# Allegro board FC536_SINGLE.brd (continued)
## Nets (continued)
HSIO171PB0: TP249.1(TP) U1.AG3(HSIO171PB0-DDR_N_0_DQS_P-NW_PLL)
HSIO172NB0: TP250.1(TP) U1.AG1(HSIO172NB0-DDR_N_0_DQ)
HSIO172PB0: TP251.1(TP) U1.AF1(HSIO172PB0-DDR_N_0_DQ-PIO_CLKIN)
HSIO173NB0: TP252.1(TP) U1.AD4(HSIO173NB0-DDR_N_0_DQ-NW_DTEST_)
HSIO173PB0: TP253.1(TP) U1.AF3(HSIO173PB0-DDR_N_0_DQ-PIO_CLKIN)
JTAG_TCK: TP314.1(TP) U1.L11(JTAG_TCK)
JTAG_TDI: TP315.1(TP) U1.K11(JTAG_TDI)
JTAG_TDO: TP316.1(TP) U1.L8(JTAG_TDO)
JTAG_TMS: TP317.1(TP) U1.L9(JTAG_TMS)
JTAG_TRSTB: TP318.1(TP) U1.H10(JTAG_TRSTB)
SC_EXIT_FLASH_FREEZE_B: TP326.1(TP) U1.H11(SC_EXIT_FLASH_FREEZE_B)
SC_IO_CFG_INTERFACE: TP325.1(TP) U1.J11(SC_IO_CFG_INTERFACE)
SC_SPI_ENABLE: TP324.1(TP) U1.L17(SC_SPI_ENABLE)
SC_SPI_SCK: TP323.1(TP) U1.L14(SC_SPI_SCK)
SC_SPI_SDI: TP322.1(TP) U1.K13(SC_SPI_SDI)
SC_SPI_SDO: TP321.1(TP) U1.K14(SC_SPI_SDO)
SC_SPI_SS: TP320.1(TP) U1.K8(SC_SPI_SS)
SERDES_0_INT_REFCLK_N: TP348.1(TP) U1.U28(SERDES_0_INT_REFCLK_N)
SERDES_0_INT_REFCLK_P: TP347.1(TP) U1.U27(SERDES_0_INT_REFCLK_P)
SERDES_0_RX0_N: TP328.1(TP) U1.G30(SERDES_0_RX0_N)
SERDES_0_RX0_P: TP327.1(TP) U1.H30(SERDES_0_RX0_P)
SERDES_0_RX1_N: TP330.1(TP) U1.K30(SERDES_0_RX1_N)
SERDES_0_RX1_P: TP329.1(TP) U1.L30(SERDES_0_RX1_P)
SERDES_0_RX2_N: TP332.1(TP) U1.Y30(SERDES_0_RX2_N)
SERDES_0_RX2_P: TP331.1(TP) U1.AA30(SERDES_0_RX2_P)
SERDES_0_RX3_N: TP334.1(TP) U1.AC30(SERDES_0_RX3_N)
SERDES_0_RX3_P: TP333.1(TP) U1.AD30(SERDES_0_RX3_P)
SERDES_0_TX0_N: TP340.1(TP) U1.D30(SERDES_0_TX0_N)
SERDES_0_TX0_P: TP339.1(TP) U1.E30(SERDES_0_TX0_P)
SERDES_0_TX1_N: TP342.1(TP) U1.N30(SERDES_0_TX1_N)
SERDES_0_TX1_P: TP341.1(TP) U1.P30(SERDES_0_TX1_P)
SERDES_0_TX2_N: TP344.1(TP) U1.U30(SERDES_0_TX2_N)
SERDES_0_TX2_P: TP343.1(TP) U1.V30(SERDES_0_TX2_P)
SERDES_0_TX3_N: TP346.1(TP) U1.AG30(SERDES_0_TX3_N)
SERDES_0_TX3_P: TP345.1(TP) U1.AF30(SERDES_0_TX3_P)
SERDES_0N_EXT_REFCLK_N: TP336.1(TP) U1.Y27(SERDES_0N_EXT_REFCLK_N)
SERDES_0N_EXT_REFCLK_P: TP335.1(TP) U1.Y28(SERDES_0N_EXT_REFCLK_P)
SERDES_0S_EXT_REFCLK_N: TP338.1(TP) U1.P28(SERDES_0S_EXT_REFCLK_N)
SERDES_0S_EXT_REFCLK_P: TP337.1(TP) U1.P27(SERDES_0S_EXT_REFCLK_P)
SERDES_VREF: C98.1 C99.1 U1.L27(SERDES_VREF_1) U1.L28(SERDES_VREF_2)

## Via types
v1: diameter 0.305, hole 0.152, TOP to BOTTOM, 372 vias

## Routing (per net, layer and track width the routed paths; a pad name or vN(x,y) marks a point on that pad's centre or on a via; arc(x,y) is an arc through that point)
GND: length 84.5
  TOP w0.203: U1.AG13 v1(56.78,50.75) ; U1.E1 v1(50.22,61.96) ; U1.V4 v1(51.85,55.25) ; U1.N19 v1(59.28,57.68) U1.P18 ; U1.T30 v1(65.41,56.46) ; U1.L24 v1(62.28,59.18) U1.K25 ; U1.N12 v1(56.28,57.75) ; U1.A1 v1(50.57,64.31) ; U1.Y21 v1(60.35,54.25) ; U1.V21 v1(60.28,55.75) U1.U20 ; U1.L26 v1(63.28,59.18) ; U1.U24 v1(62.28,55.75) ; U1.Y23 v1(61.78,54.25) ; U1.N23 v1(61.28,57.68) U1.P22 ; U1.AE30 v1(65.41,51.96) ; U1.P20 v1(60.28,57.68) U1.N21 ; U1.AG24 v1(62.28,50.75) ; U1.E21 v1(60.78,62.18) ; U1.P6 v1(52.85,57.25) ; U1.AD7 v1(53.35,52.25) ; U1.K28 v1(64.28,59.68) ; v1(63.35,54.18) U1.AA27 U1.AA28 ; U1.R1 v1(50.22,56.96) ; U1.J14 v1(56.85,60.18) ; U1.AA5 v1(52.35,53.75) ; U1.AA23 v1(61.78,53.75) ; U1.K5 52.42,59.61 52.42,59.66 v1(52.36,59.72) ; U1.AK26 v1(63.07,49.12) ; U1.V26 v1(62.78,55.75) U1.U25 ; U1.N17 v1(58.78,58.18) ; v1(64.75,58.31) 64.9,58.46 U1.M30 ; U1.A26 v1(63.07,64.31) ; U1.AE1 v1(50.22,51.96) ; U1.K22 v1(60.85,59.25) ; U1.R30 64.93,56.96 v1(64.74,57.15) ; U1.N27 63.5,57.96 v1(63.28,57.75) U1.N26 ; U1.G7 v1(53.35,61.18) ; 64.05,55.46 v1(64.26,55.24) ; U1.AF21 v1(60.78,51.25) ; U1.A16 v1(58.07,64.31) ; U1.V14 v1(57.28,55.25) ; U1.AC26 v1(63.28,52.75) ; U1.P25 v1(62.78,57.68) ; U1.U13 v1(56.78,56.18) ; U1.H24 v1(62.28,60.68) ; U1.L23 v1(61.78,59.18) ; U1.AA25 v1(62.78,53.75) ; U1.J30 v1(65.41,59.96) ; U1.V27 U1.V28 ; U1.K10 v1(55.28,59.25) ; U1.N28 v1(64.28,58.18) ; U1.N14 v1(57.28,58.18) ; U1.V17 v1(58.78,55.68) ; U1.Y26 v1(63.28,54.68) ; U1.D4 v1(51.85,62.68) ; U1.P11 v1(55.35,57.68) ; U1.AK6 v1(53.07,49.12) ; U1.P24 v1(62.28,57.68) ; U1.AE17 v1(58.78,51.75) ; U1.A6 v1(53.07,64.31) ; U1.V12 v1(56.28,55.68) ; U1.H26 v1(63.28,60.68) ; U1.M18 v1(59.28,58.68) ; U1.F17 v1(58.78,61.68) ; U1.F30 v1(65.41,61.46) ; U1.H28 v1(64.28,60.68) ; U1.AF26 v1(63.28,51.25) ; U1.C30 v1(65.41,62.96) ; U1.U11 v1(55.35,56.18) ; U1.P13 v1(56.78,57.68) ; U1.V19 v1(59.28,55.75) U1.U18 ; U1.AF10 v1(54.85,51.25) ; U1.AC28 v1(64.28,52.75) ; U1.AK16 v1(58.07,49.12) ; U1.AA10 v1(54.85,53.75) ; U1.AB30 v1(65.41,53.46) ; U1.W30 v1(65.41,54.96) ; U1.W18 v1(58.85,54.75) ; U1.AK30 v1(65.07,49.12) ; U1.D13 v1(56.35,62.68) ; U1.U22 v1(61.28,55.75) U1.V23 ; U1.K23 v1(61.35,59.68) ; U1.W13 v1(56.35,54.75) ; U1.AB14 v1(56.85,53.25) ; U1.E10 v1(54.85,62.18) ; U1.K27 v1(63.78,59.68) ; U1.Y24 v1(62.28,54.25) ; U1.AC24 v1(62.28,52.75) ; U1.E26 v1(63.28,62.18) ; U1.AH30 v1(65.41,50.46) ; U1.AG4 v1(51.85,50.75) ; U1.D24 v1(61.85,62.68)
  BOTTOM w0.203: v1(53.35,52.25) 53.74,52.63 53.74,52.92 53.62,53.04 C54.1
  BOTTOM w0.254: C46.1 58.37,61.53 58.53,61.68 v1(58.78,61.68) 58.83,61.72 C73.2 ; C50.1 59.59,58.68 v1(59.28,58.68) 59.24,58.63 C17.1 ; v1(54.85,62.18) 55.01,62.02 C75.2 ; C59.2 56.82,53.28 v1(56.85,53.25) 57.64,53.25 C10.1 ; v1(61.78,54.25) 61.51,54.52 C19.1 ; C13.1 56.61,57.51 v1(56.78,57.68) ; v1(63.28,51.25) 63.2,51.33 C24.1 ; C56.2 50.5,47.6 v1(50.51,47.58) ; C66.2 62.31,50.72 v1(62.28,50.75) 62.33,50.8 C65.2 ; C51.1 58.78,58.17 v1(58.78,58.18) ; v1(63.28,59.18) 63.34,59.12 C32.1 ; C90.2 52.15,53.95 v1(52.35,53.75) 52.38,53.72 C63.2 ; v1(58.78,55.68) 59.19,56.08 C9.1 ; v1(51.85,62.68) 52.07,62.9 C94.2 ; C43.1 62.5,56.03 v1(62.78,55.75) ; C96.2 64.25,58.22 v1(64.28,58.18) ; v1(55.35,57.68) 55.18,57.5 C52.1 ; C2.1 56.78,56.52 v1(56.78,56.18) ; C15.1 60.81,59.2 v1(60.85,59.25) ; v1(51.85,50.75) 51.85,50.75 C21.1 ; C35.1 64.18,60.58 v1(64.28,60.68) ; v1(64.28,52.75) 64.36,52.82 C41.1 ; C30.1 61,51.25 v1(60.78,51.25) 60.77,51.26 C67.2 ; C12.1 54.45,55.22 v1(54.34,55.11) 53.96,55.11 C22.1 ; C1.1 56.43,55.9 56.28,55.75 v1(56.28,55.68) ; C68.2 58.83,51.79 v1(58.78,51.75) 58.83,51.7 C69.2 ; C27.1 55.09,59.44 v1(55.28,59.25) 55.32,59.21 C85.2 ; C8.1 59.11,56.72 v1(58.85,56.97) ; C62.2 56.92,50.88 v1(56.78,50.75) ; v1(61.72,56.72) 61.7,56.74 C14.1 ; C58.2 52.83,50.41 v1(52.99,50.25) ; C3.1 61.31,57.65 v1(61.28,57.68) 61.42,57.82 C38.1 ; C77.2 53.31,64.07 v1(53.07,64.31) ; v1(62.78,57.68) 62.56,57.45 C44.1 ; v1(64.75,58.31) 64.75,58.35 64.87,58.46 C99.2 ; v1(60.78,62.18) 60.76,62.2 C82.2 ; v1(48.6,54.47) 48.62,54.48 C87.2 ; v1(57.94,55.93) 58.17,55.7 C16.1 ; v1(57.86,57.99) 57.76,57.89 C29.1 ; v1(54.85,53.75) 54.86,53.75 C64.2 ; C95.2 52.3,59.57 52.36,59.62 v1(52.36,59.72) 52.36,59.75 52.7,60.1 52.72,60.1 52.77,60.15 C53.1 ; C89.2 C91.2 52.75,57.35 v1(52.85,57.25) ; v1(56.35,62.68) 56.41,62.73 C74.2 ; C76.2 66.95,63.96 v1(66.97,63.97) ; C84.2 53.48,58.67 v1(53.43,58.62) ; v1(57.28,58.18) 57.4,58.3 C48.1 ; C25.1 60.27,54.33 v1(60.35,54.25) ; v1(64.73,53.6) 64.73,53.59 C36.1 ; v1(63.28,52.75) 63.11,52.92 C42.1 ; C39.1 61.35,55.69 v1(61.28,55.75) 61.26,55.77 C6.1 ; v1(61.78,53.75) 61.87,53.66 C71.2 ; v1(61.78,59.18) 61.85,59.18 62.02,59.01 C72.2 ; C80.2 63.08,62.38 v1(63.28,62.18) ; C7.1 59.39,55.64 v1(59.28,55.75) ; v1(59.28,57.68) 59.21,57.61 C5.1 ; C45.1 62.48,60.37 62.28,60.56 v1(62.28,60.68) ; v1(55.56,65.9) 55.58,65.89 C79.2 ; C57.2 55.58,47.6 v1(55.59,47.58) ; v1(58.85,54.75) 58.83,54.72 C20.1 ; C61.2 54.97,51.36 v1(54.85,51.25) 54.64,51.25 54.38,51.5 C31.1 ; C11.1 56.35,54.74 v1(56.35,54.75) 56.67,54.75 C18.1 ; C47.1 53.42,61.25 v1(53.35,61.18) ; v1(64.26,55.24) 64.24,55.22 C97.2 ; C86.2 50.54,52.28 v1(50.22,51.96) ; v1(57.28,55.25) 57.33,55.29 C23.1 ; C55.1 56.23,57.8 v1(56.28,57.75) ; C60.2 53.29,49.34 v1(53.07,49.12) ; C4.1 57.87,56.84 v1(57.84,56.87) 57.82,56.89 C28.1 ; C37.1 62.82,56.76 v1(62.76,56.82) ; v1(60.56,65.93) 60.58,65.91 C78.2 ; v1(61.35,59.68) 61.24,59.79 C26.1 ; C98.2 65.34,60.04 v1(65.41,59.96) ; v1(64.74,57.15) 64.95,56.94 C40.1 ; v1(48.65,59.45) 48.67,59.46 C92.2 ; v1(49.72,60.27) 49.73,60.26 C93.2 ; C83.2 62.2,62.33 v1(61.85,62.68) ; C88.2 51.85,55.25 v1(51.85,55.25) ; C49.1 56.82,60.15 v1(56.85,60.18) 56.92,60.11 C81.2 ; C70.2 60.58,47.57 v1(60.59,47.56) ; v1(62.28,54.25) 62.16,54.37 C33.1 ; C34.1 62.34,59.23 v1(62.28,59.18)
VDD: length 13.8
  TOP w0.203: U1.P12 v1(55.85,57.68) ; U1.V22 v1(60.85,55.25) ; U1.V18 v1(58.85,55.25) ; U1.V13 v1(56.35,55.25) ; U1.N13 v1(56.78,58.18) ; U1.U21 v1(60.78,55.75) ; U1.V11 v1(55.35,55.68) ; U1.N18 v1(58.85,57.75) ; U1.N20 v1(60.28,58.18) ; U1.P19 v1(59.78,57.68) ; U1.P14 v1(57.28,57.68) ; U1.U19 v1(59.78,55.75) ; U1.P21 v1(60.78,57.68) ; U1.V20 v1(60.28,55.25) ; U1.W17 v1(58.35,54.75) ; U1.U12 v1(55.85,55.75) ; U1.N22 v1(60.85,58.18) ; U1.U17 v1(58.35,56.18)
  BOTTOM w0.203: v1(58.35,54.75) 57.96,54.35 57.96,54.17 C10.2
  BOTTOM w0.254: C17.2 60.27,58.17 v1(60.28,58.18) ; C9.2 59.79,55.75 v1(59.78,55.75) ; C4.2 58.47,56.29 v1(58.35,56.18) ; C11.2 55.85,55.75 v1(55.85,55.75) 55.83,55.77 C1.2 ; v1(56.35,55.25) 56.4,55.25 56.65,55.49 C18.2 ; C14.2 60.47,56.74 v1(60.21,57) ; C3.2 60.71,57.61 v1(60.78,57.68) ; C6.2 60.66,55.87 v1(60.78,55.75) ; C15.2 60.81,58.22 v1(60.85,58.18) ; C7.2 60.24,55.3 v1(60.28,55.25) ; v1(55.58,56.7) 55.58,56.69 C2.2 ; C8.2 59.95,56.72 v1(60.21,56.45) ; C12.2 55.24,55.57 v1(55.35,55.68) ; v1(58.85,55.25) 58.83,55.23 58.45,55.23 C16.2 ; v1(55.85,57.68) 55.85,57.44 C13.2 ; v1(59.78,57.68) 59.81,57.65 C5.2
VDD18: length 5.1
  TOP w0.203: U1.Y9 v1(54.35,54.25) ; U1.W14 v1(57.28,54.75) ; U1.AF4 v1(51.85,51.25) ; U1.Y22 v1(60.85,54.25) ; U1.AF27 v1(63.78,51.25) ; U1.Y20 v1(59.85,54.25) ; U1.Y18 v1(59.28,54.25)
  BOTTOM w0.203: C20.2 58.89,53.85 v1(59.28,54.25)
  BOTTOM w0.254: v1(57.28,54.75) 57.34,54.69 C23.2 ; C24.2 63.8,51.26 v1(63.78,51.25) ; C19.2 60.91,54.31 v1(60.85,54.25) ; v1(59.85,54.25) 59.67,54.43 C25.2 ; v1(51.85,51.25) 51.75,51.35 C21.2 ; v1(54.35,54.25) 54.24,54.36 C22.2
VDD25: length 4.8
  TOP w0.203: U1.AC8 v1(54.28,52.75) ; U1.J10 v1(55.28,60.18) ; U1.H23 v1(61.78,60.68) ; U1.U14 v1(57.28,55.75) ; U1.P17 v1(58.35,57.25) ; U1.AC23 v1(61.35,52.75)
  BOTTOM w0.254: v1(57.28,55.75) 57.28,55.75 C28.2 ; C31.2 54.38,52.65 v1(54.28,52.75) ; C30.2 61.26,52.66 v1(61.35,52.75) ; C27.2 55.15,60.04 v1(55.28,60.18) ; C26.2 61.61,60.85 v1(61.78,60.68) ; C29.2 58.36,57.26 v1(58.35,57.25)
VDDA: length 7.1
  TOP w0.203: U1.AA26 v1(63.28,53.75) ; U1.H27 v1(63.78,60.68) ; U1.L25 v1(62.78,59.18) ; U1.P26 v1(63.28,57.25) ; U1.Y25 v1(62.78,54.25) ; U1.K26 v1(63.28,59.68) ; U1.U26 v1(63.28,55.75) ; U1.N24 v1(62.28,58.18) ; U1.V24 v1(62.28,55.25) ; U1.AC27 v1(63.78,52.75)
  BOTTOM w0.254: v1(63.28,53.75) 63.43,53.75 63.58,53.59 C36.2 ; v1(62.28,58.18) 62.27,58.19 C38.2 ; v1(63.78,52.75) 63.76,52.77 C41.2 ; v1(63.28,55.75) 63.17,55.86 C37.2 ; v1(63.78,60.68) 63.78,60.58 63.65,60.45 63.65,60.25 C35.2 ; v1(63.86,56.7) 63.88,56.72 C40.2 ; v1(62.78,59.18) 62.78,58.89 C32.2 ; C33.2 62.76,54.27 v1(62.78,54.25) ; C34.2 63.24,59.64 v1(63.28,59.68) ; C39.2 62.28,55.24 v1(62.28,55.25)
VDDA25: length 3.3
  TOP w0.203: U1.U23 v1(61.78,55.75) ; U1.AA24 v1(62.28,53.75) ; U1.P23 v1(61.78,57.68) ; U1.K24 v1(61.85,59.68)
  BOTTOM w0.254: v1(62.28,53.75) 62.38,53.65 62.38,53.4 C42.2 ; C43.2 61.9,55.87 v1(61.78,55.75) ; v1(61.78,57.68) 61.96,57.51 C44.2 ; C45.2 61.85,60.2 v1(61.85,59.68)
VDDAUX2: length 4.6
  TOP w0.203: U1.G18 v1(59.28,61.18) ; U1.M17 v1(58.78,58.68) ; U1.L13 v1(56.78,58.75) ; U1.M14 v1(57.28,58.68) ; U1.L18 v1(59.28,59.18) ; U1.H8 v1(54.28,60.68)
  BOTTOM w0.254: C48.2 57.53,58.9 57.31,58.68 v1(57.28,58.68) ; v1(56.78,58.75) 56.82,58.78 C49.2 ; C47.2 54.14,60.83 v1(54.28,60.68) ; C51.2 58.69,58.77 v1(58.78,58.68) ; C50.2 59.62,59.31 59.41,59.31 v1(59.28,59.18) ; C46.2 59.25,61.21 v1(59.28,61.18)
VDDAUX4: length 3.3
  TOP w0.203: U1.K9 v1(54.35,59.68) ; U1.U10 54.89,56.14 v1(54.89,56.41) ; U1.AA9 v1(54.35,53.75) ; U1.N11 v1(55.35,58.18)
  BOTTOM w0.254: v1(54.35,59.68) 54.35,59.87 C53.2 ; C54.2 54.22,53.62 v1(54.35,53.75) ; C52.2 54.75,56.55 v1(54.89,56.41) ; C55.2 55.39,58.14 v1(55.35,58.18)
VDDI0: length 7.4
  TOP w0.203: U1.AC7 v1(53.35,52.75) ; U1.AK1 v1(50.57,49.12) ; U1.AF5 v1(52.35,51.25) ; U1.AH8 v1(54.07,50.12) ; U1.AK11 v1(55.57,49.12) ; U1.AE14 v1(56.85,51.75) ; U1.AD11 v1(55.78,52.25) ; U1.Y13 v1(56.35,54.25) ; U1.Y10 v1(54.85,54.25)
  BOTTOM w0.254: v1(55.57,49.12) 55.58,49.11 C57.1 ; C58.1 52.46,51.35 v1(52.35,51.25) ; C62.1 57.12,51.48 v1(56.85,51.75) ; v1(55.78,52.25) 55.61,52.25 C61.1 ; C56.1 50.5,49.04 v1(50.57,49.12) ; v1(54.07,50.12) 53.89,49.94 C60.1 ; v1(56.35,54.25) 56.35,54.25 C59.1 ; C64.1 54.96,54.35 v1(54.85,54.25) ; C63.1 53.1,53.17 53.1,53.05 53.35,52.79 v1(53.35,52.75)
VDDI1: length 5.3
  TOP w0.203: U1.AA22 v1(60.85,53.75) ; U1.AG27 v1(63.78,50.75) ; U1.AG18 v1(59.28,50.75) ; U1.AB17 v1(58.78,53.25) ; U1.AK21 v1(60.57,49.12) ; U1.AD24 v1(62.28,52.25) ; U1.AD20 v1(60.28,52.25)
  BOTTOM w0.254: C68.1 58.83,53.2 v1(58.78,53.25) ; C67.1 60.33,52.21 v1(60.28,52.25) ; C66.1 63.76,50.72 v1(63.78,50.75) ; v1(59.28,50.75) 59.18,50.86 C69.1 ; v1(62.28,52.25) 62.33,52.2 C65.1 ; C71.1 61.23,53.37 v1(60.85,53.75) ; v1(60.57,49.12) 60.58,49.11 C70.1
VDDI2: length 9.8
  TOP w0.203: U1.G11 v1(55.78,61.18) ; U1.A30 v1(65.41,63.96) ; U1.A21 v1(60.57,64.31) ; U1.D27 v1(63.78,62.68) ; U1.G20 v1(60.28,61.18) ; U1.L22 v1(61.28,59.18) ; U1.D18 v1(59.28,62.68) ; U1.J17 v1(58.78,59.75) ; U1.F14 v1(56.85,61.68) ; U1.A11 v1(55.57,64.31) ; U1.G24 v1(62.28,61.18) ; U1.C8 v1(53.85,63.18)
  BOTTOM w0.254: C81.1 58.64,59.75 v1(58.78,59.75) ; v1(60.57,64.31) 60.58,64.3 C78.1 ; C76.1 65.42,63.96 v1(65.41,63.96) ; C73.1 59.26,62.66 v1(59.28,62.68) ; v1(55.57,64.31) 55.58,64.32 C79.1 ; v1(56.85,61.68) 56.82,61.71 C74.1 ; v1(53.85,63.18) 53.86,63.18 C77.1 ; v1(63.78,62.68) 63.78,62.75 C80.1 ; v1(60.28,61.18) 60.33,61.22 C82.1 ; v1(62.28,61.18) 62.33,61.23 C83.1 ; v1(55.78,61.18) 55.56,61.18 C75.1 ; C72.1 61.42,59.04 v1(61.28,59.18)
VDDI3: length 1.7
  TOP w0.203: U1.L10 v1(54.85,58.75) ; U1.M13 v1(56.35,58.68)
  BOTTOM w0.254: v1(54.85,58.75) 54.78,58.67 C84.1 ; v1(56.35,58.68) 56.21,58.83 C85.1
VDDI4: length 8.3
  TOP w0.203: U1.L7 v1(53.35,59.18) ; U1.H3 v1(51.35,60.25) ; U1.P10 v1(54.85,57.68) ; U1.N4 v1(51.85,58.18) ; U1.K1 v1(50.22,59.46) ; U1.Y7 v1(53.35,54.25) ; U1.U6 v1(52.85,55.75) ; U1.E5 v1(52.35,62.18) ; U1.AC3 v1(51.22,52.96) ; U1.Y1 v1(50.22,54.46)
  BOTTOM w0.254: C93.1 51.34,60.26 v1(51.35,60.25) ; C91.1 51.85,58.01 v1(51.85,58.18) ; C88.1 52.81,55.7 v1(52.85,55.75) ; C90.1 53.31,54.2 v1(53.35,54.25) ; v1(50.22,54.46) 50.2,54.48 C87.1 ; C94.1 52.64,62.46 v1(52.35,62.18) ; v1(54.85,57.68) 54.82,57.71 C89.1 ; C92.1 50.22,59.46 v1(50.22,59.46) ; v1(53.35,59.18) 53.32,59.21 C95.1 ; C86.1 51.14,52.88 v1(51.22,52.96)
VDDSREF: length 1.4
  TOP w0.203: U1.V25 v1(62.78,55.25) ; U1.N25 v1(62.78,58.18)
  BOTTOM w0.254: C97.1 62.81,55.22 v1(62.78,55.25) ; v1(62.78,58.18) 62.82,58.22 C96.1
DEVRST_N: length 7.2
  TOP w0.076: U1.J13 v1(56.35,60.18)
  SIG2 w0.076: v1(56.35,60.18) 56.64,59.89 56.99,59.89 57.23,60.13 57.23,61.8 56.85,62.18 56.85,65.79
GPIO0NB2: length 4.8
  TOP w0.076: U1.G14 v1(56.85,61.18)
  SIG1 w0.076: v1(56.85,61.18) 56.89,61.18 57.17,61.46 57.17,61.9 56.97,62.1 56.97,62.32 57.08,62.43 57.08,65.37
GPIO0PB2: length 5.2
  TOP w0.076: U1.H14 v1(56.85,60.68)
  SIG1 w0.076: v1(56.85,60.68) 57.58,61.41 57.58,65.3
GPIO1NB2: length 3.4
  TOP w0.076: U1.C14 56.83,63.2 56.83,66.22
GPIO1PB2: length 3.4
  TOP w0.076: 56.33,66.22 56.33,63.2 U1.C13
GPIO2NB2: length 3.7
  TOP w0.076: U1.E13 v1(56.35,62.18)
  SIG1 w0.076: v1(56.35,62.18) 56.35,62.28 56.67,62.6 56.67,65.44 56.7,65.46 56.7,65.48
GPIO2PB2: length 4.2
  TOP w0.076: U1.F13 v1(56.35,61.68)
  SIG1 w0.076: v1(56.35,61.68) 56.75,62.08 56.75,62.39 56.88,62.51 56.88,65.35
GPIO3NB2: length 2.3
  TOP w0.076: U1.A14 57.07,66.22
GPIO3PB2: length 2.3
  TOP w0.076: U1.A15 57.57,66.22
GPIO4NB2: length 4.7
  TOP w0.076: U1.G13 v1(56.35,61.18)
  SIG1 w0.076: 56.38,65.33 56.38,64.1 56.09,63.8 56.09,62.8 56.08,62.79 56.08,61.56 56.09,61.55 56.09,61.45 v1(56.35,61.18)
GPIO4PB2: length 5.5
  TOP w0.076: U1.H13 v1(56.35,60.68)
  SIG2 w0.076: 56.07,65.79 56.07,60.96 v1(56.35,60.68)
GPIO5NB2: length 3.9
  TOP w0.076: U1.D14 57.33,62.72 57.33,63.86 57.33,63.86 57.33,66.22
GPIO5PB2: length 3.4
  TOP w0.076: U1.E14 v1(57.28,62.18)
  SIG1 w0.076: v1(57.28,62.18) 57.28,65.3
GPIO6NB2: length 7.1
  TOP w0.076: U1.L21 v1(60.35,59.18)
  SIG1 w0.076: 66.83,59.23 64.9,59.23 64.52,58.85 60.68,58.85 v1(60.35,59.18)
GPIO6PB2: length 7.1
  TOP w0.076: U1.L20 v1(60.28,58.75)
  SIG1 w0.076: v1(60.28,58.75) 60.38,58.65 65.22,58.65 65.48,58.9 66.93,58.9
GPIO7NB2: length 6.4
  TOP w0.076: U1.J18 v1(58.85,60.18)
  SIG2 w0.076: v1(58.85,60.18) 58.41,60.18 58.06,60.52 58.06,60.81 58.24,60.99 58.24,61.8 58.78,62.33 58.78,65.41
GPIO7PB2: length 5.5
  TOP w0.076: U1.H18 v1(59.28,60.68)
  SIG1 w0.076: 59.03,65.3 59.03,63.65 58.45,63.08 58.45,61.51 v1(59.28,60.68)
GPIO8NB2: length 5.1
  TOP w0.076: U1.H17 v1(58.35,60.68)
  SIG1 w0.076: v1(58.35,60.68) 58.04,60.99 58.04,63.32 58.57,63.86 58.57,65.13
GPIO8PB2: length 5.1
  TOP w0.076: U1.G17 v1(58.78,60.75)
  SIG1 w0.076: v1(58.78,60.75) 58.24,61.29 58.24,63.24 58.78,63.77 58.78,65.13
GPIO9NB2: length 6.5
  TOP w0.076: v1(58.22,59.39) 58.3,59.46 U1.K17
  SIG1 w0.076: v1(58.22,59.39) 58.22,59.65 57.74,60.14 57.74,61.28 57.78,61.32 57.78,65.3
GPIO9PB2: length 8.5
  TOP w0.076: U1.K18 v1(59.28,59.68)
  SIG2 w0.076: v1(59.28,59.68) 59.8,59.16 59.8,58.79 60.13,58.47 60.55,58.47 60.88,58.8 66.62,58.8
GPIO10NB2: length 6.5
  TOP w0.076: U1.K21 v1(60.78,59.68)
  SIG1 w0.076: v1(60.78,59.68) 61.08,59.98 64.99,59.98 65.33,59.64 66.7,59.64
GPIO10PB2: length 6.7
  TOP w0.076: U1.K20 v1(60.28,59.68)
  SIG2 w0.076: 66.32,60.43 65.15,60.43 64.74,60.02 60.62,60.02 v1(60.28,59.68)
GPIO11NB2: length 5.6
  TOP w0.076: U1.H20 v1(60.28,60.68)
  SIG2 w0.076: v1(60.28,60.68) 59.98,60.98 59.98,61.38 60.24,61.63 60.24,65.75
GPIO11PB2: length 6
  TOP w0.076: U1.J20 v1(59.85,60.18)
  SIG2 w0.076: 59.56,65.75 59.56,60.47 v1(59.85,60.18)
GPIO12NB2: length 3.5
  TOP w0.076: U1.E18 v1(59.28,62.18)
  SIG1 w0.076: 59.58,65.25 59.58,62.48 v1(59.28,62.18)
GPIO12PB2: length 4.4
  TOP w0.076: U1.F18 v1(59.28,61.68)
  SIG1 w0.076: 59.23,65.43 59.23,63.4 58.83,62.99 58.83,62.14 v1(59.28,61.68)
GPIO13NB2: length 3.4
  TOP w0.076: U1.C18 59.31,63.2 59.31,66.22
GPIO13PB2: length 3.4
  TOP w0.076: U1.C17 58.33,63.2 58.33,64.19 58.36,64.22 58.36,66.22
GPIO14NB2: length 4.4
  TOP w0.076: 58.81,66.22 58.81,62.2 U1.E17
GPIO14PB2: length 4.1
  TOP w0.076: 57.78,66.19 57.78,64.22 57.83,64.17 57.83,63.2 U1.D17
GPIO15NB2: length 2.3
  TOP w0.076: U1.A18 59.07,66.22
GPIO15PB2: length 2.3
  TOP w0.076: U1.A17 58.57,66.22
GPIO16NB2: length 3.4
  TOP w0.076: U1.E20 v1(59.85,62.18)
  SIG1 w0.076: v1(59.85,62.18) 59.85,65.31
GPIO16PB2: length 4.2
  TOP w0.076: U1.F20 v1(59.85,61.68)
  SIG1 w0.076: v1(59.85,61.68) 60.2,62.02 60.2,62.53 60.06,62.68 60.06,65.33
GPIO17NB2: length 2.3
  TOP w0.076: U1.A19 59.57,66.22
GPIO17PB2: length 2.3
  TOP w0.076: U1.A20 60.07,66.22
GPIO18NB2: length 2.3
  TOP w0.076: U1.A23 61.57,66.22
GPIO18PB2: length 2.3
  TOP w0.076: U1.A22 61.07,66.22
GPIO19NB2: length 3.4
  TOP w0.076: U1.C24 62.31,63.2 62.31,66.22
GPIO19PB2: length 3.4
  TOP w0.076: 61.81,66.22 61.81,63.2 U1.C23
GPIO20NB2: length 3.6
  TOP w0.076: U1.C27 64.31,63.7 64.31,66.22
GPIO20PB2: length 3.4
  TOP w0.076: U1.C26 63.07,63.62 63.32,63.88 63.32,64.19 63.38,64.24 63.38,66.22
GPIO21NB2: length 2.3
  TOP w0.076: U1.A25 62.57,66.22
GPIO21PB2: length 2.3
  TOP w0.076: U1.A24 62.07,66.22
GPIO22NB2: length 2.3
  TOP w0.076: U1.A28 64.07,66.22
GPIO22PB2: length 2.3
  TOP w0.076: U1.A27 63.57,66.22
GPIO23NB2: length 2.1
  TOP w0.076: U1.B30 67.21,63.46
GPIO23PB2: length 2.3
  TOP w0.076: U1.A29 64.57,66.22
GPIO24NB2: length 6.4
  TOP w0.076: U1.H21 v1(60.78,60.68)
  SIG1 w0.076: 66.57,60.48 65.38,60.48 65.09,60.18 61.28,60.18 v1(60.78,60.68)
GPIO24PB2: length 6.5
  TOP w0.076: U1.J21 v1(60.35,60.18)
  SIG2 w0.076: v1(60.35,60.18) 60.55,60.38 64.67,60.38 65,60.71 66.32,60.71
GPIO25NB2: length 3.4
  TOP w0.076: 60.86,66.22 60.86,64.22 60.81,64.17 60.81,63.2 U1.C21
GPIO25PB2: length 3.4
  TOP w0.076: 59.83,66.22 59.83,63.2 U1.C20
GPIO26NB2: length 4.2
  TOP w0.076: U1.F21 v1(60.78,61.68)
  SIG1 w0.076: v1(60.78,61.68) 61.07,61.96 61.07,63.61 61.21,63.75 61.21,65.41
GPIO26PB2: length 4.4
  TOP w0.076: U1.G21 v1(60.78,61.18)
  SIG1 w0.076: v1(60.78,61.18) 60.45,61.51 60.45,62.79 60.26,62.98 60.26,65.02
GPIO27NB2: length 3.2
  TOP w0.076: U1.D21 v1(60.78,62.68)
  SIG1 w0.076: 60.99,65.46 60.99,64.06 60.78,63.86 v1(60.78,62.68)
GPIO27PB2: length 3.9
  TOP w0.076: U1.D20 60.33,62.72 60.33,64.17 60.25,64.25 60.25,66.22
GPIO28NB2: length 4.1
  TOP w0.076: U1.F23 v1(61.35,61.68)
  SIG1 w0.076: 61.52,65.41 61.52,63.77 61.35,63.6 v1(61.35,61.68)
GPIO28PB2: length 4.7
  TOP w0.076: U1.G23 v1(61.78,61.18)
  SIG1 w0.076: 62.41,65.35 62.41,61.8 v1(61.78,61.18)
GPIO29NB2: length 3.9
  TOP w0.076: U1.D23 61.31,62.72 61.31,66.22
GPIO29PB2: length 3.7
  TOP w0.076: U1.E23 v1(61.78,62.18)
  SIG1 w0.076: v1(61.78,62.18) 61.56,62.41 61.56,63.36 61.8,63.6 61.8,65.38
GPIO30NB2: length 4.6
  TOP w0.076: U1.E24 62.81,62.71 62.81,64.19 62.75,64.25 62.75,66.22
GPIO30PB2: length 4.1
  TOP w0.076: U1.D26 63.31,62.7 63.31,63.12 63.81,63.62 63.81,66.22
GPIO31NB2: length 4.9
  TOP w0.076: U1.G25 v1(62.78,61.18)
  SIG1 w0.076: 63.45,65.46 63.45,64.03 62.78,63.37 v1(62.78,61.18)
GPIO31PB2: length 4.1
  TOP w0.076: U1.F24 v1(61.85,61.68)
  SIG1 w0.076: 62.18,65.38 62.18,62.01 v1(61.85,61.68)
GPIO32NB2: length 3.3
  TOP w0.076: U1.E27 v1(63.78,62.18)
  SIG1 w0.076: 66.62,62.66 64.27,62.66 v1(63.78,62.18)
GPIO32PB2: length 3.9
  TOP w0.076: U1.E28 64.77,62.67 64.77,63.01 64.97,63.2 65.28,63.2 65.32,63.25 67.21,63.25
GPIO33NB2: length 4
  TOP w0.076: U1.G26 v1(63.28,61.18)
  SIG1 w0.076: 66.52,62.26 64.36,62.26 v1(63.28,61.18)
GPIO33PB2: length 4.2
  TOP w0.076: U1.H25 v1(62.78,60.68)
  SIG1 w0.076: 66.47,60.68 64.87,60.68 64.57,60.38 63.08,60.38 v1(62.78,60.68)
GPIO34NB2: length 3.9
  TOP w0.076: U1.D28 64.57,62.96 64.57,63.32 64.97,63.72 65.28,63.72 65.35,63.65 67.21,63.65
GPIO34PB2: length 3.9
  TOP w0.076: 67.21,64.26 64.97,64.26 64.81,64.1 64.81,63.82 64.31,63.32 64.31,63.2 U1.C28
GPIO35NB2: length 2.5
  TOP w0.076: U1.G28 v1(64.28,61.18)
  SIG1 w0.076: v1(64.28,61.18) 66.47,61.18
GPIO35PB2: length 3.4
  TOP w0.076: U1.G27 v1(63.78,61.18)
  SIG1 w0.076: v1(63.78,61.18) 64.17,61.57 65.05,61.57 65.38,61.9 66.55,61.9
GPIO174NB4: length 4.9
  TOP w0.076: 47.29,53.22 50.67,53.22 50.69,53.25 51.78,53.25 U1.AC4
GPIO174PB4: length 4.4
  TOP w0.076: 47.29,52.7 50.67,52.7 50.91,52.46 U1.AD3
GPIO175NB4: length 3.3
  TOP w0.076: U1.AD1 47.29,52.46
GPIO175PB4: length 3.3
  TOP w0.076: U1.AC1 47.29,52.96
GPIO176NB4: length 3.3
  TOP w0.076: U1.AB1 47.29,53.46
GPIO176PB4: length 3.3
  TOP w0.076: U1.AA1 47.29,53.96
GPIO177NB4: length 4.6
  TOP w0.076: U1.AC6 v1(52.85,52.75)
  SIG1 w0.076: v1(52.85,52.75) 52.28,52.17 51.18,52.17 51.03,52.32 48.9,52.32
GPIO177PB4: length 3.8
  TOP w0.076: U1.AC5 v1(52.35,52.75)
  SIG1 w0.076: v1(52.35,52.75) 51.93,52.75 51.79,52.6 48.9,52.6
GPIO178NB4: length 4.3
  TOP w0.076: U1.Y6 v1(52.85,54.68)
  SIG1 w0.076: 49.1,54.15 51.21,54.15 51.38,54.33 52.5,54.33 v1(52.85,54.68)
GPIO178PB4: length 3.9
  TOP w0.076: U1.Y5 v1(52.35,54.68)
  SIG1 w0.076: v1(52.35,54.68) 50.83,54.68 50.52,54.99 48.9,54.99
GPIO179NB4: length 4.9
  TOP w0.076: U1.AA7 v1(53.35,53.75)
  SIG1 w0.076: v1(53.35,53.75) 52.84,53.24 51.65,53.24 51.4,53.49 49.1,53.49
GPIO179PB4: length 4.3
  TOP w0.076: U1.AA6 v1(52.85,53.75)
  SIG1 w0.076: v1(52.85,53.75) 52.55,53.44 51.97,53.44 51.71,53.7 49.1,53.7
GPIO180NB4: length 4.9
  TOP w0.076: 47.29,54.75 50.31,54.75 50.34,54.72 51.81,54.72 U1.Y4
GPIO180PB4: length 4.4
  TOP w0.076: 47.29,54.19 50.11,54.19 50.11,54.19 50.34,54.19 50.37,54.22 51.33,54.22 U1.Y3
GPIO181NB4: length 5.4
  TOP w0.076: U1.Y8 v1(53.85,54.25)
  SIG1 w0.076: v1(53.85,54.25) 53.54,54.56 53.19,54.56 52.73,54.1 51.51,54.1 51.36,53.95 49.1,53.95
GPIO181PB4: length 5.5
  TOP w0.076: U1.AA8 v1(53.85,53.75)
  SIG1 w0.076: 49.1,53.29 51.32,53.29 51.57,53.04 53.14,53.04 v1(53.85,53.75)
GPIO182NB4: length 4.4
  TOP w0.076: 47.29,53.72 51.33,53.72 U1.AA3
GPIO183NB4: length 5.4
  TOP w0.076: U1.V10 v1(54.85,55.68)
  SIG2 w0.076: v1(54.85,55.68) 54.85,55.79 54.63,56.01 54.63,56.29 54.41,56.52 50.37,56.52
GPIO183PB4: length 5.3
  TOP w0.076: U1.V9 v1(54.35,55.68)
  SIG2 w0.076: 49.89,55.8 52.42,55.8 52.68,56.06 53.06,56.06 53.72,55.4 54.07,55.4 v1(54.35,55.68)
GPIO184NB4: length 4
  TOP w0.076: U1.V5 v1(52.35,55.25)
  SIG1 w0.076: v1(52.35,55.25) 52.27,55.25 51.96,55.56 48.81,55.56
GPIO184PB4: length 3.9
  TOP w0.076: U1.U5 v1(52.35,56.18)
  SIG1 w0.076: 48.84,56.28 49.94,56.28 49.94,56.28 50.51,56.28 50.51,56.28 52.25,56.28 v1(52.35,56.18)
GPIO185NB4: length 4.4
  TOP w0.076: 47.29,55.22 51.33,55.22 U1.V3
GPIO185PB4: length 4.9
  TOP w0.076: 47.29,56.2 51.83,56.2 U1.U4
GPIO186NB4: length 6.6
  TOP w0.076: U1.U9 v1(54.35,56.18)
  SIG1 w0.076: v1(54.35,56.18) 53.79,56.74 52.77,56.74 52.51,57.01 50.62,57.01 50.28,57.34 48.58,57.34
GPIO186PB4: length 5.5
  TOP w0.076: U1.U8 v1(53.85,56.18)
  SIG1 w0.076: v1(53.85,56.18) 53.49,56.54 52.69,56.54 52.54,56.69 50.34,56.69 50.34,56.69 50.11,56.69 50.11,56.69 48.84,56.69
GPIO187NB4: length 3.3
  TOP w0.076: U1.W1 47.29,54.96
GPIO187PB4: length 3.3
  TOP w0.076: U1.V1 47.29,55.46
GPIO188NB4: length 4.9
  TOP w0.076: U1.U7 v1(53.35,56.18)
  SIG1 w0.076: 48.84,56.48 50.02,56.48 50.02,56.48 50.42,56.48 50.42,56.48 52.46,56.48 52.6,56.34 53.19,56.34 v1(53.35,56.18)
GPIO188PB4: length 4.6
  TOP w0.076: U1.V6 v1(52.85,55.25)
  SIG1 w0.076: v1(52.85,55.25) 52.52,55.58 52.22,55.58 51.93,55.87 50.68,55.87 50.67,55.87 49.77,55.87 48.84,55.87
GPIO189NB4: length 5.6
  TOP w0.076: U1.V8 v1(53.85,55.68)
  SIG1 w0.076: v1(53.85,55.68) 53.42,55.68 53.04,56.06 52.7,56.06 52.55,55.9 52.24,55.9 52.06,56.08 50.59,56.08 50.59,56.08 49.85,56.08 49.85,56.08 48.84,56.08
GPIO189PB4: length 5.1
  TOP w0.076: U1.V7 v1(53.35,55.25)
  SIG1 w0.076: v1(53.35,55.25) 53.06,54.96 51.19,54.96 50.85,55.3 48.84,55.3
GPIO198NB4: length 4.4
  TOP w0.076: U1.U3 51.33,55.72 47.29,55.72
GPIO198PB4: length 4.4
  TOP w0.076: U1.P3 51.33,57.22 50.47,57.22 50.43,57.26 47.29,57.26
GPIO199NB4: length 3.3
  TOP w0.076: U1.U1 47.29,55.96
GPIO199PB4: length 3.3
  TOP w0.076: U1.T1 47.29,56.46
GPIO202NB4: length 5.4
  TOP w0.076: 47.29,57.7 52.33,57.7 U1.P5
GPIO202PB4: length 4.4
  TOP w0.076: U1.N5 v1(52.35,58.18)
  SIG1 w0.076: v1(52.35,58.18) 52.03,57.86 50.98,57.86 50.66,58.18 48.56,58.18
GPIO203NB4: length 5.1
  TOP w0.076: 47.29,56.68 50.31,56.68 50.35,56.72 51.32,56.72 U1.P4
GPIO203PB4: length 4.4
  TOP w0.076: U1.N3 50.99,57.96 50.75,58.2 47.29,58.2
GPIO204NB4: length 3.8
  TOP w0.076: U1.P9 v1(54.35,57.25)
  SIG2 w0.076: 51.03,56.92 54.03,56.92 v1(54.35,57.25)
GPIO204PB4: length 6
  TOP w0.076: U1.P8 v1(53.85,57.25)
  SIG1 w0.076: v1(53.85,57.25) 53.34,57.76 52.66,57.76 52.32,57.41 50.79,57.41 50.43,57.77 48.62,57.77
GPIO205NB4: length 3.3
  TOP w0.076: U1.P1 47.29,57.46
GPIO205PB4: length 3.3
  TOP w0.076: U1.N1 47.29,57.96
GPIO206NB4: length 3.3
  TOP w0.076: U1.M1 47.29,58.46
GPIO206PB4: length 3.3
  TOP w0.076: U1.L1 47.29,58.96
GPIO207NB4: length 5.5
  TOP w0.076: U1.P7 v1(53.35,57.25)
  SIG1 w0.076: 48.62,57.57 50.34,57.57 50.7,57.21 52.4,57.21 52.75,57.56 53.12,57.56 53.35,57.33 v1(53.35,57.25)
GPIO207PB4: length 4.9
  TOP w0.076: U1.N6 v1(52.85,58.18)
  SIG1 w0.076: v1(52.85,58.18) 52.79,58.18 52.23,57.62 50.87,57.62 50.51,57.97 48.64,57.97
GPIO208NB4: length 5.3
  TOP w0.076: 47.29,60.2 49.1,60.2 49.33,59.97 49.83,59.97 50.06,60.2 50.72,60.2 51.01,59.92 51.61,59.92 U1.K4
GPIO208PB4: length 4.5
  TOP w0.076: U1.K3 51.33,59.7 50.37,59.7 50.34,59.74 50.11,59.74 49.98,59.62 49.05,59.62 48.88,59.79 47.29,59.79
GPIO209NB4: length 6.4
  TOP w0.076: U1.N9 v1(54.35,58.18)
  SIG2 w0.076: v1(54.35,58.18) 53.76,57.58 48.54,57.58
GPIO209PB4: length 5.4
  TOP w0.076: U1.N10 v1(54.85,58.18)
  SIG2 w0.076: 51.08,56.72 54.33,56.72 54.64,57.03 54.64,57.35 54.48,57.51 54.48,57.81 v1(54.85,58.18)
GPIO210NB4: length 4.1
  TOP w0.076: U1.L5 v1(52.35,58.75)
  SIG1 w0.076: v1(52.35,58.75) 52.28,58.82 50.88,58.82 50.72,58.66 48.62,58.66
GPIO210PB4: length 4.7
  TOP w0.076: U1.L6 v1(52.85,58.75)
  SIG1 w0.076: 48.62,58.86 50.64,58.86 50.8,59.03 52.57,59.03 v1(52.85,58.75)
GPIO211NB4: length 5.2
  TOP w0.076: U1.N7 v1(53.35,58.18)
  SIG1 w0.076: 48.62,58.46 53.08,58.46 v1(53.35,58.18)
GPIO211PB4: length 5.2
  TOP w0.076: U1.N8 v1(53.85,58.18)
  SIG2 w0.076: 49.1,57.81 53.48,57.81 v1(53.85,58.18)
GPIO212NB4: length 4.9
  TOP w0.076: 47.29,59.15 50.29,59.15 50.34,59.2 51.83,59.2 U1.L4
GPIO212PB4: length 4.4
  TOP w0.076: 47.29,58.72 51.33,58.72 U1.L3
GPIO213NB4: length 5.3
  TOP w0.076: U1.K7 v1(53.35,59.68)
  SIG1 w0.076: 48.62,59.75 50.66,59.75 50.98,59.43 53.11,59.43 v1(53.35,59.68)
GPIO213PB4: length 4.9
  TOP w0.076: v1(52.85,59.73) 52.85,59.68 U1.K6
  SIG1 w0.076: 48.62,59.96 50.94,59.96 51.13,59.77 51.96,59.77 52.19,60 52.59,60 v1(52.85,59.73)
GPIO214NB4: length 3.4
  TOP w0.076: 47.31,59.96 49.01,59.96 49.18,59.79 49.9,59.79 50.07,59.96 U1.J1
GPIO214PB4: length 3
  TOP w0.076: 47.66,60.58 50.36,60.58 50.48,60.46 U1.H1
GPIO215NB4: length 5.1
  TOP w0.076: U1.G4 51.61,61.42 51.13,61.42 50.83,61.72 50.36,61.72 50.3,61.66 47.29,61.66
GPIO215PB4: length 4.4
  TOP w0.076: 47.29,61.2 51.33,61.2 U1.G3
GPIO216NB4: length 4.2
  TOP w0.076: U1.H5 v1(52.35,60.68)
  SIG1 w0.076: 48.62,61 52.03,61 v1(52.35,60.68)
GPIO216PB4: length 4.9
  TOP w0.076: 47.31,60.78 50.41,60.78 50.47,60.72 51.81,60.72 U1.H4
GPIO217NB4: length 3.3
  TOP w0.076: U1.G1 50.53,61 47.29,61
GPIO217PB4: length 3.3
  TOP w0.076: U1.F1 47.29,61.46
GPIO218NB4: length 5.5
  TOP w0.076: 47.29,63.22 50.65,63.22 50.99,62.89 50.99,62.58 51.34,62.22 51.81,62.22 U1.E4
GPIO218PB4: length 4.7
  TOP w0.076: U1.E3 51.16,61.96 50.81,62.31 50.81,62.56 50.65,62.72 47.29,62.72
GPIO219NB4: length 4.8
  TOP w0.076: U1.H6 v1(52.85,60.68)
  SIG1 w0.076: 48.62,61.21 52.32,61.21 v1(52.85,60.68)
GPIO219PB4: length 5.8
  TOP w0.076: 47.29,62.26 50.3,62.26 50.34,62.22 50.65,62.22 51.28,61.59 51.94,61.59 U1.G5
GPIO238NB5: length 3.3
  TOP w0.076: U1.C1 47.29,62.96
GPIO238PB5: length 3.3
  TOP w0.076: U1.B1 47.29,63.46
GPIO239NB5: length 3.3
  TOP w0.076: U1.D1 47.29,62.46
GPIO239PB5: length 5
  TOP w0.076: 47.29,63.7 50.73,63.7 51.2,63.24 51.2,62.83 U1.D3
GPIO240NB5: length 3.4
  TOP w0.076: 52.33,66.22 52.33,63.78 52.57,63.54 U1.C5
GPIO240PB5: length 4.1
  TOP w0.076: U1.D5 52.33,62.7 52.33,63.19 51.83,63.69 51.83,66.22
GPIO241NB5: length 2.3
  TOP w0.076: U1.A2 51.07,66.22
GPIO241PB5: length 2.3
  TOP w0.076: U1.A3 51.57,66.22
GPIO242NB5: length 2.3
  TOP w0.076: U1.A4 52.07,66.22
GPIO242PB5: length 2.3
  TOP w0.076: U1.A5 52.57,66.22
GPIO243NB5: length 3.6
  TOP w0.076: U1.C4 52.07,62.97 51.31,63.73 51.31,66.22
GPIO243PB5: length 3.6
  TOP w0.076: U1.C3 51.57,63.12 50.81,63.88 50.81,64.17 50.85,64.21 50.85,66.22
GPIO244NB2: length 5.3
  TOP w0.076: U1.H7 v1(53.35,60.68)
  SIG1 w0.076: v1(53.35,60.68) 53.08,60.4 52.03,60.4 51.64,60.79 48.62,60.79
GPIO244PB2: length 4.7
  TOP w0.076: U1.G6 v1(52.85,61.18)
  SIG1 w0.076: v1(52.85,61.18) 52.51,61.52 48.62,61.52
GPIO245NB2: length 4.1
  TOP w0.076: 53.83,66.22 53.83,63.86 54.31,63.38 54.31,62.7 U1.D8
GPIO245PB2: length 6.3
  TOP w0.076: U1.E8 v1(53.85,62.18)
  SIG1 w0.076: 48.46,63.63 52.4,63.63 v1(53.85,62.18)
GPIO246NB2: length 5.6
  TOP w0.076: U1.E7 v1(53.35,62.18)
  SIG1 w0.076: v1(53.35,62.18) 52.36,63.17 48.46,63.17
GPIO246PB2: length 5.2
  TOP w0.076: v1(53.3,61.67) 53.5,61.46 U1.F7
  SIG1 w0.076: 48.69,62.36 50.93,62.36 51.39,61.9 53.07,61.9 v1(53.3,61.67)
GPIO247NB2: length 4.7
  TOP w0.076: U1.G8 v1(54.28,61.18)
  SIG1 w0.076: v1(54.28,61.18) 53.95,61.51 53.95,61.85 54.14,62.03 54.14,65.36
GPIO247PB2: length 4
  TOP w0.076: U1.F8 v1(54.28,61.68)
  SIG1 w0.076: v1(54.28,61.68) 54.28,61.9 54.34,61.95 54.34,65.36
GPIO248NB2: length 2.3
  TOP w0.076: U1.A8 54.07,66.22
GPIO248PB2: length 2.3
  TOP w0.076: U1.A7 53.57,66.22
GPIO249NB2: length 3.4
  TOP w0.076: U1.C7 53.33,63.2 53.33,64.19 53.36,64.22 53.36,66.22
GPIO249PB2: length 4.1
  TOP w0.076: U1.D7 52.81,63.22 52.81,64.06 52.75,64.13 52.75,66.22
GPIO250NB2: length 4.1
  TOP w0.076: 54.33,66.22 54.33,63.71 54.58,63.45 54.58,62.95 U1.D10
GPIO250PB2: length 3.4
  TOP w0.076: 54.83,66.22 54.83,63.2 U1.C10
GPIO251NB2: length 2.3
  TOP w0.076: U1.A9 54.57,66.22
GPIO251PB2: length 2.3
  TOP w0.076: U1.A10 55.07,66.22
GPIO252NB2: length 3.6
  TOP w0.076: U1.E11 v1(55.78,62.18)
  SIG1 w0.076: 56.11,65.33 56.11,64.21 55.78,63.89 v1(55.78,62.18)
GPIO252PB2: length 4.3
  TOP w0.076: U1.F11 v1(55.78,61.68)
  SIG1 w0.076: 54.99,65.33 54.99,64.11 55.48,63.62 55.48,61.99 v1(55.78,61.68)
GPIO253NB2: length 3.9
  TOP w0.076: U1.D11 55.31,62.72 55.31,64.19 55.25,64.25 55.25,66.22
GPIO253PB2: length 3.4
  TOP w0.076: 55.87,66.22 55.87,64.23 55.83,64.19 55.83,63.22 U1.C11
GPIO254NB2: length 4.8
  TOP w0.076: U1.G10 v1(54.85,61.18)
  SIG1 w0.076: v1(54.85,61.18) 55.23,61.56 55.23,63.58 54.79,64.03 54.79,65.33
GPIO254PB2: length 4.6
  TOP w0.076: U1.F10 v1(54.85,61.68)
  SIG1 w0.076: v1(54.85,61.68) 54.54,61.99 54.54,65.37 54.7,65.53 54.87,65.53 54.88,65.52 54.9,65.52
GPIO255NB2: length 2.3
  TOP w0.076: U1.A13 56.57,66.22
GPIO255PB2: length 2.3
  TOP w0.076: U1.A12 56.07,66.22
HSIO72NB1: length 3.9
  TOP w0.076: U1.AJ30 68.95,49.96
HSIO72PB1: length 2.8
  TOP w0.076: U1.AK29 64.57,46.62
HSIO73NB1: length 5.6
  TOP w0.076: U1.AF28 64.07,51.45 64.59,50.93 64.59,50.57 64.96,50.2 65.3,50.2 65.32,50.18 68.93,50.18
HSIO73PB1: length 5.7
  TOP w0.076: U1.AG28 64.34,50.69 64.34,50.35 64.98,49.71 69.01,49.71
HSIO74NB1: length 3.9
  TOP w0.076: U1.AH26 63.07,50.02 63.33,49.76 63.33,49.24 63.37,49.19 63.37,46.66
HSIO74PB1: length 4.6
  TOP w0.076: 63.81,46.71 63.81,49.56 63.32,50.05 63.32,50.71 U1.AG26
HSIO75NB1: length 2.8
  TOP w0.076: U1.AK28 64.07,46.62
HSIO75PB1: length 2.8
  TOP w0.076: U1.AK27 63.57,46.62
HSIO76NB1: length 4.2
  TOP w0.076: U1.AH28 64.07,50.46 64.08,50.44 64.08,50.33 64.81,49.61 64.81,49.36 64.78,49.34 64.78,46.58
HSIO76PB1: length 4.1
  TOP w0.076: U1.AH27 63.57,50.4 64.31,49.66 64.31,46.63
HSIO77NB1: length 3.5
  TOP w0.076: U1.AD28 v1(64.28,52.25)
  SIG1 w0.076: 67.26,52.68 64.72,52.68 v1(64.28,52.25)
HSIO77PB1: length 3.9
  TOP w0.076: U1.AD27 v1(63.78,52.25)
  SIG1 w0.076: 67.08,52.32 65.33,52.32 64.97,51.97 64.06,51.97 v1(63.78,52.25)
HSIO78NB1: length 5
  TOP w0.076: U1.AD25 v1(62.78,52.25)
  SIG1 w0.076: v1(62.78,52.25) 63.47,51.56 64.29,51.56 64.59,51.26 67.08,51.26
HSIO78PB1: length 4.6
  TOP w0.076: U1.AE24 v1(61.85,51.75)
  SIG1 w0.076: 62.28,48.11 62.28,49.33 62.85,49.9 62.85,50.75 v1(61.85,51.75)
HSIO79NB1: length 4.9
  TOP w0.076: U1.AC25 v1(62.78,52.75)
  SIG1 w0.076: v1(62.78,52.75) 63.08,53.04 64.75,53.04 64.87,53.16 67.18,53.16
HSIO79PB1: length 4.4
  TOP w0.076: U1.AD26 v1(63.28,52.25)
  SIG1 w0.076: v1(63.28,52.25) 63.77,51.77 65.2,51.77 65.46,51.51 67.08,51.51
HSIO80NB1: length 5.2
  TOP w0.076: 62.78,46.62 62.78,49.21 62.81,49.24 62.81,50.72 U1.AF24
HSIO80PB1: length 4.5
  TOP w0.076: 61.82,46.61 61.82,50.71 U1.AG23
HSIO81NB1: length 5.2
  TOP w0.076: U1.AE23 v1(61.78,52.18)
  SIG1 w0.076: v1(61.78,52.18) 61.94,52.18 63.07,51.05 63.07,49.77 62.51,49.21 62.51,48.13
HSIO81PB1: length 3.7
  TOP w0.076: U1.AF23 v1(61.78,51.25)
  SIG1 w0.076: v1(61.78,51.25) 61.78,47.81
HSIO82NB1: length 3.9
  TOP w0.076: 61.31,46.66 61.31,50.2 U1.AH23
HSIO82PB1: length 3.9
  TOP w0.076: U1.AH24 62.31,50.22 62.31,46.63
HSIO83NB1: length 4.3
  TOP w0.076: U1.AD23 v1(61.78,52.68)
  SIG1 w0.076: 61.5,48.95 61.5,51.39 61.35,51.54 61.35,52.25 v1(61.78,52.68)
HSIO83PB1: length 7
  TOP w0.076: U1.AB21 v1(60.78,53.25)
  SIG1 w0.076: 67.1,54.13 64.7,54.13 64.69,54.13 64.2,54.13 63.53,53.45 60.99,53.45 v1(60.78,53.25)
HSIO84NB1: length 2.8
  TOP w0.076: U1.AK25 62.57,46.62
HSIO84PB1: length 2.8
  TOP w0.076: U1.AK24 62.07,46.62
HSIO85NB1: length 3.3
  TOP w0.076: U1.AG21 v1(60.78,50.75)
  SIG1 w0.076: 60.95,47.83 60.95,49.49 60.78,49.66 v1(60.78,50.75)
HSIO85PB1: length 4
  TOP w0.076: U1.AH21 60.81,50.22 60.81,49.25 60.89,49.17 60.89,46.63
HSIO86NB1: length 4.4
  TOP w0.076: U1.AE21 v1(60.78,51.75)
  SIG1 w0.076: 61.21,47.8 61.21,51.32 v1(60.78,51.75)
HSIO86PB1: length 4.5
  TOP w0.076: U1.AE20 v1(59.85,51.75)
  SIG1 w0.076: v1(59.85,51.75) 59.92,51.75 60.3,51.37 60.3,50.55 60.31,50.54 60.31,50.02 59.87,49.58 59.87,47.96
HSIO87NB1: length 2.8
  TOP w0.076: U1.AK23 61.57,46.62
HSIO87PB1: length 2.8
  TOP w0.076: U1.AK22 61.07,46.62
HSIO88NB1: length 3.8
  TOP w0.076: U1.AF20 v1(59.85,51.25)
  SIG1 w0.076: 59.64,48.03 59.64,49.64 60.08,50.08 60.08,51.02 v1(59.85,51.25)
HSIO88PB1: length 4.5
  TOP w0.076: 60.27,46.59 60.27,49.2 60.31,49.24 60.31,50.72 U1.AG20
HSIO89NB1: length 7.2
  TOP w0.076: U1.AC21 v1(60.35,52.75)
  SIG1 w0.076: v1(60.35,52.75) 60.75,52.75 61.25,53.25 63.77,53.25 64.4,53.88 64.89,53.88 65.06,53.71 65.27,53.71 65.35,53.79 66.71,53.79
HSIO89PB1: length 4.9
  TOP w0.076: U1.AD21 v1(60.78,52.25)
  SIG1 w0.076: v1(60.78,52.25) 60.51,51.97 60.51,51.87 60.51,51.86 60.51,50.63 60.51,50.63 60.51,49.77 60.15,49.4 60.15,47.9
HSIO90NB1: length 2.8
  TOP w0.076: U1.AK20 60.07,46.62
HSIO90PB1: length 2.8
  TOP w0.076: U1.AK19 59.57,46.62
HSIO91NB1: length 3.9
  TOP w0.076: U1.AH20 59.82,50.21 59.82,46.66
HSIO91PB1: length 3.9
  TOP w0.076: 59.31,46.63 59.31,50.22 U1.AH18
HSIO92NB1: length 2.8
  TOP w0.076: U1.AK18 59.07,46.62
HSIO92PB1: length 2.8
  TOP w0.076: U1.AK17 58.57,46.62
HSIO93NB1: length 4.5
  TOP w0.076: U1.AE18 v1(59.28,51.75)
  SIG1 w0.076: 58.9,47.92 58.98,48 58.98,50.2 58.76,50.42 58.76,50.97 58.91,51.13 58.91,51.38 v1(59.28,51.75)
HSIO93PB1: length 3.7
  TOP w0.076: U1.AF18 v1(59.28,51.25)
  SIG1 w0.076: 59.18,48.08 59.18,50.46 58.98,50.66 58.98,50.91 59.28,51.21 v1(59.28,51.25)
HSIO94NB1: length 4
  TOP w0.076: 58.37,46.61 58.37,49.21 58.32,49.26 58.32,50.21 U1.AH17
HSIO94PB1: length 2.8
  TOP w0.076: U1.AK15 57.57,46.62
HSIO95NB1: length 4.2
  TOP w0.076: U1.AF17 v1(58.35,51.25)
  SIG1 w0.076: v1(58.35,51.25) 58.35,50.16 58.57,49.94 58.57,48.1 58.45,47.98 58.43,47.98 58.35,47.9 58.35,47.56
HSIO95PB1: length 4.5
  TOP w0.076: U1.AG17 58.81,50.72 58.81,46.61
HSIO96NB1: length 5
  TOP w0.076: U1.AD18 v1(59.28,52.25)
  SIG1 w0.076: 59.39,48.03 59.39,49.73 59.85,50.19 59.85,50.83 59.58,51.11 59.58,51.96 v1(59.28,52.25)
HSIO96PB1: length 5.5
  TOP w0.076: U1.AC18 v1(59.28,52.75)
  SIG1 w0.076: v1(59.28,52.75) 58.5,51.96 58.5,51.5 58.63,51.36 58.63,51.13 58.56,51.06 58.56,50.29 58.78,50.07 58.78,48.08
HSIO97NB1: length 6
  TOP w0.076: U1.AB18 v1(59.28,53.25)
  SIG2 w0.076: 58.63,47.98 58.67,48.02 58.67,51.36 58.51,51.52 58.51,51.95 58.86,52.3 58.86,52.82 v1(59.28,53.25)
HSIO97PB1: length 8.4
  TOP w0.076: U1.AA18 v1(59.28,53.75)
  SIG2 w0.076: v1(59.28,53.75) 59.57,54.03 59.57,54.37 60.17,54.97 65,54.97 65.41,54.56 66.47,54.56
HSIO98NB1: length 6.4
  TOP w0.076: U1.AA21 v1(60.35,53.75)
  SIG2 w0.076: v1(60.35,53.75) 59.57,52.96 59.57,47.98
HSIO98PB1: length 8.6
  TOP w0.076: U1.AA20 v1(59.85,53.75)
  SIG1 w0.076: v1(59.85,53.75) 59.58,54.02 59.58,54.13 59.58,54.5 59.77,54.69 62.26,54.69 62.53,54.97 64.97,54.97 65.28,55.27 66.7,55.27
HSIO99NB1: length 4.6
  TOP w0.076: U1.AD17 v1(58.35,52.25)
  SIG1 w0.076: v1(58.35,52.25) 58.03,51.92 58.03,50.09 58.37,49.75 58.37,48.18
HSIO99PB1: length 5.3
  TOP w0.076: U1.AC17 v1(58.35,52.75)
  SIG1 w0.076: 57.76,47.98 57.76,52.15 v1(58.35,52.75)
HSIO100NB1: length 6.7
  TOP w0.076: U1.AA17 v1(58.35,53.75)
  SIG2 w0.076: 57.56,47.7 57.56,49.48 58.05,49.97 58.05,53.44 v1(58.35,53.75)
HSIO100PB1: length 7.3
  TOP w0.076: U1.Y17 v1(58.35,54.25)
  SIG2 w0.076: 57.35,47.7 57.35,49.56 57.84,50.05 57.84,53.74 v1(58.35,54.25)
HSIO101NB1: length 5.2
  TOP w0.076: U1.AC20 v1(59.85,52.75)
  SIG2 w0.076: v1(59.85,52.75) 59.85,52.24 60.2,51.89 60.2,47.98
HSIO101PB1: length 6.6
  TOP w0.076: U1.AB20 v1(60.28,53.25)
  SIG2 w0.076: v1(60.28,53.25) 60.57,52.96 60.96,52.96 61.09,53.09 66.4,53.09
HSIO144NB0: length 4
  TOP w0.076: 56.31,46.6 56.31,50.21 U1.AH13
HSIO144PB0: length 2.8
  TOP w0.076: U1.AK14 57.07,46.62
HSIO145NB0: length 3.9
  TOP w0.076: 56.82,46.68 56.82,50.22 U1.AH14
HSIO145PB0: length 4.4
  TOP w0.076: 57.31,46.61 57.31,50.72 U1.AG14
HSIO146NB0: length 4.7
  TOP w0.076: U1.AE13 v1(56.35,51.75)
  SIG1 w0.076: 56.72,47.83 56.72,49.15 57.12,49.55 57.12,50.98 v1(56.35,51.75)
HSIO146PB0: length 4.9
  TOP w0.076: U1.AD13 v1(56.35,52.25)
  SIG1 w0.076: v1(56.35,52.25) 56.08,51.97 56.08,51.03 56.24,50.86 56.24,47.83
HSIO147NB0: length 2.8
  TOP w0.076: U1.AK13 56.57,46.62
HSIO147PB0: length 2.8
  TOP w0.076: U1.AK12 56.07,46.62
HSIO148NB0: length 5.2
  TOP w0.076: 57.78,46.61 57.78,49.34 57.81,49.36 57.81,49.78 57.59,50.01 57.59,50.95 U1.AF14
HSIO148PB0: length 3.8
  TOP w0.076: U1.AF13 v1(56.35,51.25)
  SIG1 w0.076: v1(56.35,51.25) 56.49,51.11 56.49,47.83
HSIO149NB0: length 5.1
  TOP w0.076: U1.AD14 v1(56.85,52.25)
  SIG1 w0.076: v1(56.85,52.25) 57.33,51.77 57.33,49.38 56.92,48.97 56.92,47.83
HSIO149PB0: length 5.6
  TOP w0.076: U1.AC14 v1(56.85,52.75)
  SIG1 w0.076: 57.12,47.85 57.12,48.82 57.53,49.22 57.53,52.07 v1(56.85,52.75)
HSIO150NB0: length 4.4
  TOP w0.076: 54.82,46.62 54.82,50.72 U1.AG10
HSIO150PB0: length 4
  TOP w0.076: U1.AH10 55.31,50.22 55.31,49.24 55.25,49.17 55.25,46.63
HSIO151NB0: length 3.8
  TOP w0.076: U1.AF11 v1(55.78,51.25)
  SIG1 w0.076: v1(55.78,51.25) 55.78,51.03 55.91,50.91 55.91,47.83
HSIO151PB0: length 4.7
  TOP w0.076: U1.AE11 v1(55.78,51.75)
  SIG1 w0.076: v1(55.78,51.75) 55.45,51.41 55.45,51.08 55.7,50.83 55.7,49.89 55.24,49.43 55.24,47.83
HSIO152NB0: length 4
  TOP w0.076: U1.AH11 55.81,50.22 55.81,49.25 55.87,49.19 55.87,46.6
HSIO152PB0: length 3.4
  TOP w0.076: U1.AG11 v1(55.35,50.75)
  SIG1 w0.076: 55.04,47.83 55.04,49.71 55.35,50.02 v1(55.35,50.75)
HSIO153NB0: length 4.5
  TOP w0.076: U1.AE10 v1(54.85,51.75)
  SIG1 w0.076: 54.81,47.83 54.81,50.7 55.17,51.05 55.17,51.41 54.85,51.73 v1(54.85,51.75)
HSIO153PB0: length 5.5
  TOP w0.076: U1.AF8 v1(53.85,51.25)
  SIG1 w0.076: v1(53.85,51.25) 53.18,50.57 52.41,50.57 52.03,50.19 49.05,50.19
HSIO154NB0: length 2.8
  TOP w0.076: U1.AK10 55.07,46.62
HSIO154PB0: length 2.8
  TOP w0.076: U1.AK9 54.57,46.62
HSIO155NB0: length 4.6
  TOP w0.076: U1.AE8 v1(53.85,51.75)
  SIG1 w0.076: v1(53.85,51.75) 53.85,51.74 54.14,51.45 54.14,51.04 53.57,50.47 53.57,47.83
HSIO155PB0: length 5.2
  TOP w0.076: U1.AD8 v1(53.85,52.25)
  SIG1 w0.076: v1(53.85,52.25) 53.87,52.25 54.34,51.78 54.34,50.94 53.77,50.37 53.77,47.83
HSIO156NB0: length 7.2
  TOP w0.076: U1.AA13 v1(56.35,53.75)
  SIG2 w0.076: 56.74,47.7 56.74,49.82 57.22,50.29 57.22,53.38 56.84,53.75 v1(56.35,53.75)
HSIO156PB0: length 6.4
  TOP w0.076: U1.AB13 v1(56.35,53.25)
  SIG2 w0.076: v1(56.35,53.25) 56.35,53.25 55.48,52.38 55.48,51.09 56.01,50.57 56.01,47.69
HSIO157NB0: length 5.6
  TOP w0.076: U1.AC13 v1(56.35,52.75)
  SIG2 w0.076: 56.29,47.69 56.29,50.64 56.08,50.86 56.08,52.47 v1(56.35,52.75)
HSIO157PB0: length 5.4
  TOP w0.076: U1.AC11 v1(55.35,52.75)
  SIG2 w0.076: 55.04,47.75 55.04,50.98 55.19,51.13 55.19,52.59 v1(55.35,52.75)
HSIO158NB0: length 7.6
  TOP w0.076: U1.AA11 v1(55.78,53.75)
  SIG2 w0.076: v1(55.78,53.75) 54.98,54.55 53.12,54.55 52.62,54.06 49.05,54.06
HSIO158PB0: length 7
  TOP w0.076: U1.Y11 v1(55.78,54.25)
  SIG2 w0.076: 49.43,54.96 53.65,54.96 53.82,54.79 55.24,54.79 v1(55.78,54.25)
HSIO159NB0: length 4.9
  TOP w0.076: U1.AD10 v1(54.85,52.25)
  SIG1 w0.076: v1(54.85,52.25) 54.55,51.94 54.55,47.83
HSIO159PB0: length 5.5
  TOP w0.076: U1.AC10 v1(54.85,52.75)
  SIG2 w0.076: v1(54.85,52.75) 54.51,52.4 54.51,47.73
HSIO160NB0: length 7
  TOP w0.076: U1.AB11 v1(55.35,53.25)
  SIG2 w0.076: v1(55.35,53.25) 55.15,53.25 54.92,53.02 54.38,53.02 54.3,53.11 51.94,53.11 51.49,52.65 48.95,52.65
HSIO160PB0: length 6.4
  TOP w0.076: U1.AB10 54.92,53.31 v1(54.71,53.31)
  SIG2 w0.076: v1(54.71,53.31) 51.61,53.31 51.36,53.57 48.82,53.57
HSIO161NB0: length 6.6
  TOP w0.076: U1.AA14 v1(57.28,53.75)
  SIG2 w0.076: 56.95,47.7 56.95,49.73 57.42,50.2 57.42,53.61 v1(57.28,53.75)
HSIO161PB0: length 7.2
  TOP w0.076: U1.Y14 v1(57.28,54.25)
  SIG2 w0.076: v1(57.28,54.25) 57.64,53.9 57.64,50.13 57.15,49.65 57.15,47.7
HSIO162NB0: length 2.8
  TOP w0.076: U1.AK7 53.57,46.62
HSIO162PB0: length 2.8
  TOP w0.076: U1.AK8 54.07,46.62
HSIO163NB0: length 5
  TOP w0.076: U1.AF7 v1(53.35,51.25)
  SIG1 w0.076: 49.05,50.42 51.97,50.42 52.32,50.77 52.88,50.77 v1(53.35,51.25)
HSIO163PB0: length 5
  TOP w0.076: U1.AE7 v1(53.35,51.75)
  SIG1 w0.076: v1(53.35,51.75) 52.92,51.75 52.73,51.56 50.83,51.56 50.39,51.13 48.9,51.13
HSIO164NB0: length 2.8
  TOP w0.076: U1.AK5 52.57,46.62
HSIO164PB0: length 2.8
  TOP w0.076: U1.AK4 52.07,46.62
HSIO165NB0: length 4
  TOP w0.076: U1.AH7 53.57,49.94 53.81,49.7 53.81,46.59
HSIO165PB0: length 4.5
  TOP w0.076: U1.AG8 54.35,50.68 54.35,49.59 54.33,49.56 54.33,46.64
HSIO166NB0: length 3.9
  TOP w0.076: 52.78,46.65 52.78,49.21 52.82,49.25 52.82,49.66 52.57,49.91 U1.AH5
HSIO166PB0: length 4
  TOP w0.076: 51.83,46.59 51.83,50.22 U1.AH4
HSIO167NB0: length 4.4
  TOP w0.076: 53.35,46.64 53.35,49.22 53.32,49.25 53.32,50.71 U1.AG7
HSIO167PB0: length 4.5
  TOP w0.076: 52.33,46.59 52.33,50.72 U1.AG5
HSIO168NB0: length 2.8
  TOP w0.076: U1.AK3 51.57,46.62
HSIO168PB0: length 2.8
  TOP w0.076: U1.AK2 51.07,46.62
HSIO169NB0: length 3.3
  TOP w0.076: U1.AJ1 47.29,49.96
HSIO169PB0: length 3.3
  TOP w0.076: U1.AH1 47.29,50.46
HSIO170NB0: length 4.6
  TOP w0.076: U1.AD6 v1(52.85,52.25)
  SIG1 w0.076: 48.9,51.46 50.24,51.46 50.65,51.87 52.47,51.87 v1(52.85,52.25)
HSIO170PB0: length 5.6
  TOP w0.076: U1.AD5 51.81,51.7 50.34,51.7 50.31,51.67 47.29,51.67
HSIO171NB0: length 4
  TOP w0.076: 51.33,46.59 51.33,50.22 U1.AH3
HSIO171PB0: length 4.4
  TOP w0.076: 47.29,50.72 51.33,50.72 U1.AG3
HSIO172NB0: length 3.3
  TOP w0.076: U1.AG1 47.29,50.96
HSIO172PB0: length 3.3
  TOP w0.076: U1.AF1 47.29,51.46
HSIO173NB0: length 4.9
  TOP w0.076: U1.AD4 51.8,52.2 50.68,52.2 50.67,52.2 50.36,52.2 50.28,52.29 47.29,52.29
HSIO173PB0: length 4.4
  TOP w0.076: 47.29,51.22 51.33,51.22 U1.AF3
JTAG_TCK: length 7.7
  TOP w0.076: U1.L11 v1(55.35,58.75)
  SIG2 w0.076: 48.79,59.82 51.54,59.82 51.83,60.1 53.74,60.1 53.87,59.97 54.45,59.97 54.65,59.77 54.65,59.45 v1(55.35,58.75)
JTAG_TDI: length 8.2
  TOP w0.076: U1.K11 v1(55.78,59.68)
  SIG2 w0.076: 54.18,66.02 54.18,62.01 53.87,61.71 53.87,60.58 54.05,60.4 54.65,60.4 55.25,59.79 55.67,59.79 v1(55.78,59.68)
JTAG_TDO: length 5.9
  TOP w0.076: U1.L8 v1(53.85,59.18)
  SIG1 w0.076: v1(53.85,59.18) 53.83,59.18 53.55,58.9 53.15,58.9 52.82,59.23 50.43,59.23 50.27,59.07 48.59,59.07
JTAG_TMS: length 6
  TOP w0.076: U1.L9 v1(54.35,59.18)
  SIG2 w0.076: v1(54.35,59.18) 54.07,58.9 53.16,58.9 52.95,59.11 48.83,59.11
JTAG_TRSTB: length 5.8
  TOP w0.076: U1.H10 v1(54.85,60.68)
  SIG2 w0.076: v1(54.85,60.68) 54.58,60.96 54.58,66.07
SC_EXIT_FLASH_FREEZE_B: length 5.6
  TOP w0.076: U1.H11 v1(55.78,60.68)
  SIG2 w0.076: v1(55.78,60.68) 55.5,60.97 55.5,63.38 55.04,63.83 55.04,65.66
SC_IO_CFG_INTERFACE: length 6.1
  TOP w0.076: U1.J11 v1(55.78,60.18)
  SIG2 w0.076: v1(55.78,60.18) 55.29,60.67 55.29,62.99 54.81,63.47 54.81,65.58
SC_SPI_ENABLE: length 7.7
  TOP w0.076: U1.L17 v1(58.78,59.18)
  SIG2 w0.076: v1(58.78,59.18) 58.68,59.08 58.12,59.08 57.84,59.35 57.84,60.87 58.04,61.07 58.04,62.03 58.57,62.56 58.57,65.38
SC_SPI_SCK: length 7.4
  TOP w0.076: U1.L14 v1(57.28,59.18)
  SIG2 w0.076: v1(57.28,59.18) 57.64,59.53 57.64,60.95 57.84,61.16 57.84,63.58 57.43,63.98 57.43,65.84
SC_SPI_SDI: length 8.4
  TOP w0.076: U1.K13 v1(56.35,59.68)
  SIG2 w0.076: 49.06,60.84 51.63,60.84 52.11,60.36 53.78,60.36 53.95,60.18 54.53,60.18 54.55,60.16 54.56,60.16 55.13,59.59 55.42,59.59 55.68,59.33 56.01,59.33 v1(56.35,59.68)
SC_SPI_SDO: length 6.8
  TOP w0.076: U1.K14 v1(57.28,59.68)
  SIG2 w0.076: 57.18,65.86 57.18,63.83 57.63,63.37 57.63,61.24 57.43,61.04 57.43,59.82 v1(57.28,59.68)
SC_SPI_SS: length 5.9
  TOP w0.076: U1.K8 v1(53.85,59.68)
  SIG1 w0.076: 48.62,60.59 51.5,60.59 51.89,60.2 53.33,60.2 v1(53.85,59.68)
SERDES_0_INT_REFCLK_N: length 5.7
  TOP w0.076: U1.U28 v1(64.28,56.18)
  SIG2 w0.076: 69.14,55.77 64.26,55.77 64.14,55.89 64.14,56.03 v1(64.28,56.18)
SERDES_0_INT_REFCLK_P: length 6
  TOP w0.076: U1.U27 v1(63.78,56.18)
  SIG2 w0.076: v1(63.78,56.18) 63.93,56.03 63.93,55.81 64.17,55.57 69.14,55.57
SERDES_0_RX0_N: length 4.1
  TOP w0.076: 69.08,60.81 65.22,60.81 U1.G30
SERDES_0_RX0_P: length 4.1
  TOP w0.076: 69.08,60.61 65.22,60.61 U1.H30
SERDES_0_RX1_N: length 4.1
  TOP w0.076: 69.08,59.31 65.22,59.31 U1.K30
SERDES_0_RX1_P: length 4.1
  TOP w0.076: U1.L30 65.22,59.11 69.08,59.11
SERDES_0_RX2_N: length 4.1
  TOP w0.076: 69.14,54.31 65.22,54.31 U1.Y30
SERDES_0_RX2_P: length 4.1
  TOP w0.076: 69.14,54.11 65.22,54.11 U1.AA30
SERDES_0_RX3_N: length 4.1
  TOP w0.076: U1.AC30 65.22,52.81 69.08,52.81
SERDES_0_RX3_P: length 4.1
  TOP w0.076: 69.08,52.61 65.22,52.61 U1.AD30
SERDES_0_TX0_N: length 4.1
  TOP w0.076: 69.08,62.31 65.22,62.31 U1.D30
SERDES_0_TX0_P: length 4.1
  TOP w0.076: U1.E30 65.22,62.11 69.08,62.11
SERDES_0_TX1_N: length 4.1
  TOP w0.076: U1.N30 65.22,57.81 69.14,57.81
SERDES_0_TX1_P: length 4.1
  TOP w0.076: 69.14,57.61 65.22,57.61 U1.P30
SERDES_0_TX2_N: length 4.1
  TOP w0.076: 69.14,55.81 65.22,55.81 U1.U30
SERDES_0_TX2_P: length 4.1
  TOP w0.076: 69.14,55.61 65.22,55.61 U1.V30
SERDES_0_TX3_N: length 4.1
  TOP w0.076: U1.AG30 65.22,51.11 69.08,51.11
SERDES_0_TX3_P: length 4.1
  TOP w0.076: U1.AF30 65.22,51.31 69.08,51.31
SERDES_0N_EXT_REFCLK_N: length 6.1
  TOP w0.076: U1.Y27 v1(63.78,54.68)
  SIG2 w0.076: 69.14,54.03 64.21,54.03 63.93,54.31 63.93,54.53 v1(63.78,54.68)
SERDES_0N_EXT_REFCLK_P: length 5.7
  TOP w0.076: U1.Y28 v1(64.28,54.68)
  SIG2 w0.076: 69.14,54.23 64.3,54.23 64.14,54.39 64.14,54.53 v1(64.28,54.68)
